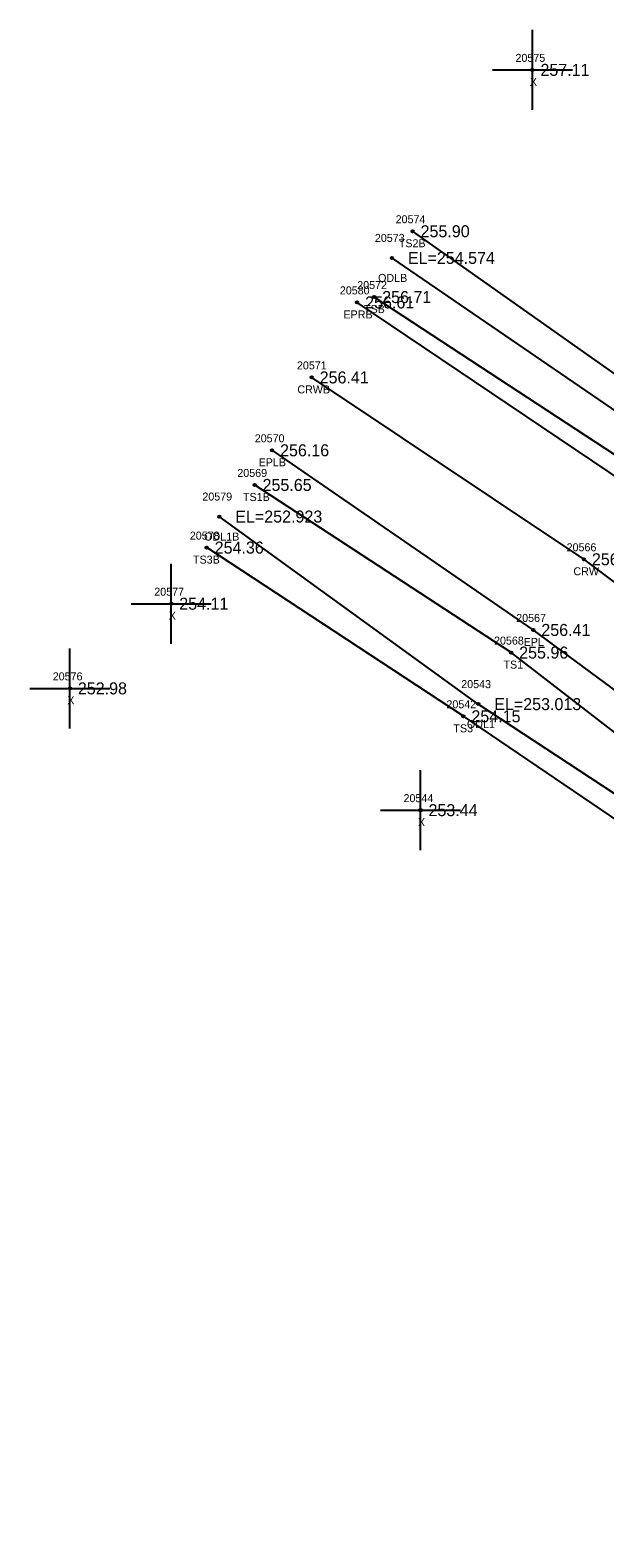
# Model space of a CAD drawing. Extents: x 1961330 to 1962287, y 800294 to 801079.
# Drawn here: x 1961329.8 to 1961401.6, y 800892.8 to 801079.3 of the extents above; entities that cross this region are included whole.
import ezdxf

# ---------------------------------------------------------------- set-up
doc = ezdxf.new("R2010")
doc.units = 0
for name, color, linetype in [('RD_DTM_BkLn1', 7, 'Continuous'), ('RD_DTM_BkLn2', 7, 'Continuous'), ('RD_DTM_BkLn_txCode', 7, 'Continuous'), ('RD_EX_H2O', 7, 'Continuous'), ('RD_EX_H2O_txCode', 7, 'Continuous'), ('RD_EX_Misc', 7, 'Continuous'), ('RD_EX_Misc_txCode', 7, 'Continuous'), ('RD_EX_Road', 7, 'Continuous'), ('RD_EX_Road_txCode', 7, 'Continuous'), ('RD_EX_TX_H2O_ELEV', 7, 'Continuous'), ('RD_EX_TX_Misc_ELEV', 7, 'Continuous'), ('RD_EX_TX_Road_ELEV', 7, 'Continuous'), ('RD_HC_Survey_ELEV', 7, 'Continuous'), ('RD_HC_Survey_txCode', 7, 'Continuous'), ('RD_SMD_Locator', 7, 'Continuous')]:
    doc.layers.add(name, color=color, linetype=linetype)

msp = doc.modelspace()

# ---------------------------------------------------------------- linework, layer by layer
at = {"layer": 'RD_DTM_BkLn1'}
msp.add_lwpolyline([(1962257.08, 800334.72), (1962203.79, 800372.43), (1962164.31, 800399.58), (1962126.58, 800429.85), (1962084.5, 800463.37), (1962045.12, 800502.48), (1962010.49, 800530.36), (1961971.27, 800562.01), (1961931.18, 800594.14), (1961890.91, 800625.98), (1961844.41, 800662.62), (1961808.07, 800691.13), (1961729.11, 800753.37), (1961696.19, 800780.32), (1961667.25, 800802.66), (1961624.93, 800836.78), (1961588.01, 800866), (1961545.37, 800899.49), (1961472.25, 800957.29), (1961437.91, 800983.99), (1961399.03, 801013.16), (1961365.01, 801035.89)], dxfattribs=at)
at = {"layer": 'RD_DTM_BkLn2'}
for points in [[(1961462.06, 800990.23), (1961461.21, 800995.11), (1961412.16, 801029.8), (1961377.62, 801054.15)], [(1961462.06, 800990.23), (1961454.06, 800991.51), (1961407.72, 801023.04), (1961372.82, 801045.93)], [(1961428.72, 800963.19), (1961432.11, 800964.86), (1961432.76, 800968.44), (1961389.94, 801001.5), (1961357.87, 801022.45)], [(1961428.72, 800963.19), (1961383.97, 800993.54), (1961351.89, 801014.62)]]:
    msp.add_lwpolyline(points, dxfattribs=at)
at = {"layer": 'RD_EX_H2O'}
for points in [[(1961462.06, 800990.23), (1961410.26, 801026.71), (1961375.03, 801050.82)], [(1961428.19, 800967.22), (1961385.82, 800995.06), (1961353.46, 801018.5)]]:
    msp.add_lwpolyline(points, dxfattribs=at)
at = {"layer": 'RD_EX_Misc'}
for p, q in [((1961392.6, 801069.32), (1961392.6, 801079.32)), ((1961387.6, 801074.32), (1961397.6, 801074.32)), ((1961347.46, 801002.61), (1961347.46, 801012.61)), ((1961342.46, 801007.61), (1961352.46, 801007.61)), ((1961334.79, 800992.03), (1961334.79, 801002.03)), ((1961329.79, 800997.03), (1961339.79, 800997.03)), ((1961378.61, 800976.81), (1961378.61, 800986.81)), ((1961373.61, 800981.81), (1961383.61, 800981.81))]:
    msp.add_line(p, q, dxfattribs=at)
at = {"layer": 'RD_EX_Road'}
for points in [[(1961651.45, 800830.73), (1961641.14, 800839.02), (1961595.18, 800874.45), (1961552.9, 800907.54), (1961510.92, 800940.49), (1961504.01, 800946.58), (1961476.53, 800968.16), (1961444.88, 800992.72), (1961406.41, 801021.23), (1961370.69, 801045.26)], [(1961660.52, 800795.31), (1961637.49, 800813.67), (1961617.86, 800829), (1961581.48, 800857.91), (1961538.42, 800891.96), (1961505, 800917.96), (1961467.33, 800947.97), (1961432.02, 800975.33), (1961392.71, 801004.33), (1961360.06, 801026.78)]]:
    msp.add_lwpolyline(points, dxfattribs=at)
at = {"layer": 'RD_SMD_Locator'}
for centre in [(1961392.6, 801074.32), (1961377.62, 801054.15), (1961375.03, 801050.82), (1961370.69, 801045.26), (1961372.82, 801045.93), (1961365.01, 801035.89), (1961360.06, 801026.78), (1961357.87, 801022.45), (1961353.46, 801018.5), (1961351.89, 801014.62), (1961399.03, 801013.16), (1961347.46, 801007.61), (1961392.71, 801004.33), (1961389.94, 801001.5), (1961334.79, 800997.03), (1961385.82, 800995.06), (1961383.97, 800993.54), (1961378.61, 800981.81)]:
    msp.add_circle(centre, 0.15, dxfattribs=at)

# ---------------------------------------------------------------- texts
at = {"layer": 'RD_DTM_BkLn_txCode'}
for s, p in [('20574', (1961375.5, 801055.15)), ('TS2B', (1961375.9, 801052.15)), ('20572', (1961370.7, 801046.93)), ('TSB', (1961371.55, 801043.93)), ('20569', (1961355.72, 801023.45)), ('TS1B', (1961356.43, 801020.45)), ('20578', (1961349.78, 801015.62)), ('TS3B', (1961350.18, 801012.62)), ('20568', (1961387.8, 801002.5)), ('TS1', (1961388.98, 800999.5)), ('20542', (1961381.85, 800994.54)), ('TS3', (1961382.72, 800991.54))]:
    msp.add_text(s, height=1, dxfattribs=at).set_placement(p)
at = {"layer": 'RD_EX_H2O_txCode'}
for s, p in [('20573', (1961372.91, 801052.82)), ('ODLB', (1961373.31, 801047.82)), ('20579', (1961351.35, 801020.5)), ('ODL1B', (1961351.58, 801015.5)), ('20543', (1961383.7, 800997.06)), ('ODL1', (1961384.41, 800992.06))]:
    msp.add_text(s, height=1, dxfattribs=at).set_placement(p)
at = {"layer": 'RD_EX_Misc_txCode'}
for s, p in [('20575', (1961390.48, 801075.32)), ('X', (1961392.28, 801072.32)), ('20577', (1961345.34, 801008.61)), ('X', (1961347.15, 801005.61)), ('20576', (1961332.65, 800998.03)), ('X', (1961334.47, 800995.03)), ('20544', (1961376.49, 800982.81)), ('X', (1961378.29, 800979.81))]:
    msp.add_text(s, height=1, dxfattribs=at).set_placement(p)
at = {"layer": 'RD_EX_Road_txCode'}
for s, p in [('20580', (1961368.53, 801046.26)), ('EPRB', (1961368.98, 801043.26)), ('20570', (1961357.9, 801027.78)), ('EPLB', (1961358.38, 801024.78)), ('20567', (1961390.57, 801005.33)), ('EPL', (1961391.5, 801002.33))]:
    msp.add_text(s, height=1, dxfattribs=at).set_placement(p)
at = {"layer": 'RD_EX_TX_H2O_ELEV'}
for s, p in [('EL=254.574', (1961377.03, 801050.07)), ('EL=252.923', (1961355.46, 801017.75)), ('EL=253.013', (1961387.82, 800994.31))]:
    msp.add_text(s, height=1.5, dxfattribs=at).set_placement(p)
at = {"layer": 'RD_EX_TX_Misc_ELEV'}
for s, p in [('257.11', (1961393.6, 801073.57)), ('255.90', (1961378.62, 801053.4)), ('256.71', (1961373.82, 801045.18)), ('255.65', (1961358.87, 801021.7)), ('254.36', (1961352.89, 801013.87)), ('254.11', (1961348.46, 801006.86)), ('255.96', (1961390.94, 801000.75)), ('252.98', (1961335.79, 800996.28)), ('254.15', (1961384.97, 800992.79)), ('253.44', (1961379.61, 800981.06))]:
    msp.add_text(s, height=1.5, dxfattribs=at).set_placement(p)
at = {"layer": 'RD_EX_TX_Road_ELEV'}
for s, p in [('256.61', (1961371.69, 801044.51)), ('256.16', (1961361.06, 801026.03)), ('256.41', (1961393.71, 801003.58))]:
    msp.add_text(s, height=1.5, dxfattribs=at).set_placement(p)
at = {"layer": 'RD_HC_Survey_ELEV'}
for s, p in [('256.41', (1961366.01, 801035.14)), ('256.73', (1961400.03, 801012.41))]:
    msp.add_text(s, height=1.5, dxfattribs=at).set_placement(p)
at = {"layer": 'RD_HC_Survey_txCode'}
for s, p in [('20571', (1961363.17, 801036.89)), ('CRWB', (1961363.22, 801033.89)), ('20566', (1961396.87, 801014.16)), ('CRW', (1961397.72, 801011.16))]:
    msp.add_text(s, height=1, dxfattribs=at).set_placement(p)

doc.saveas('drawing.dxf')
